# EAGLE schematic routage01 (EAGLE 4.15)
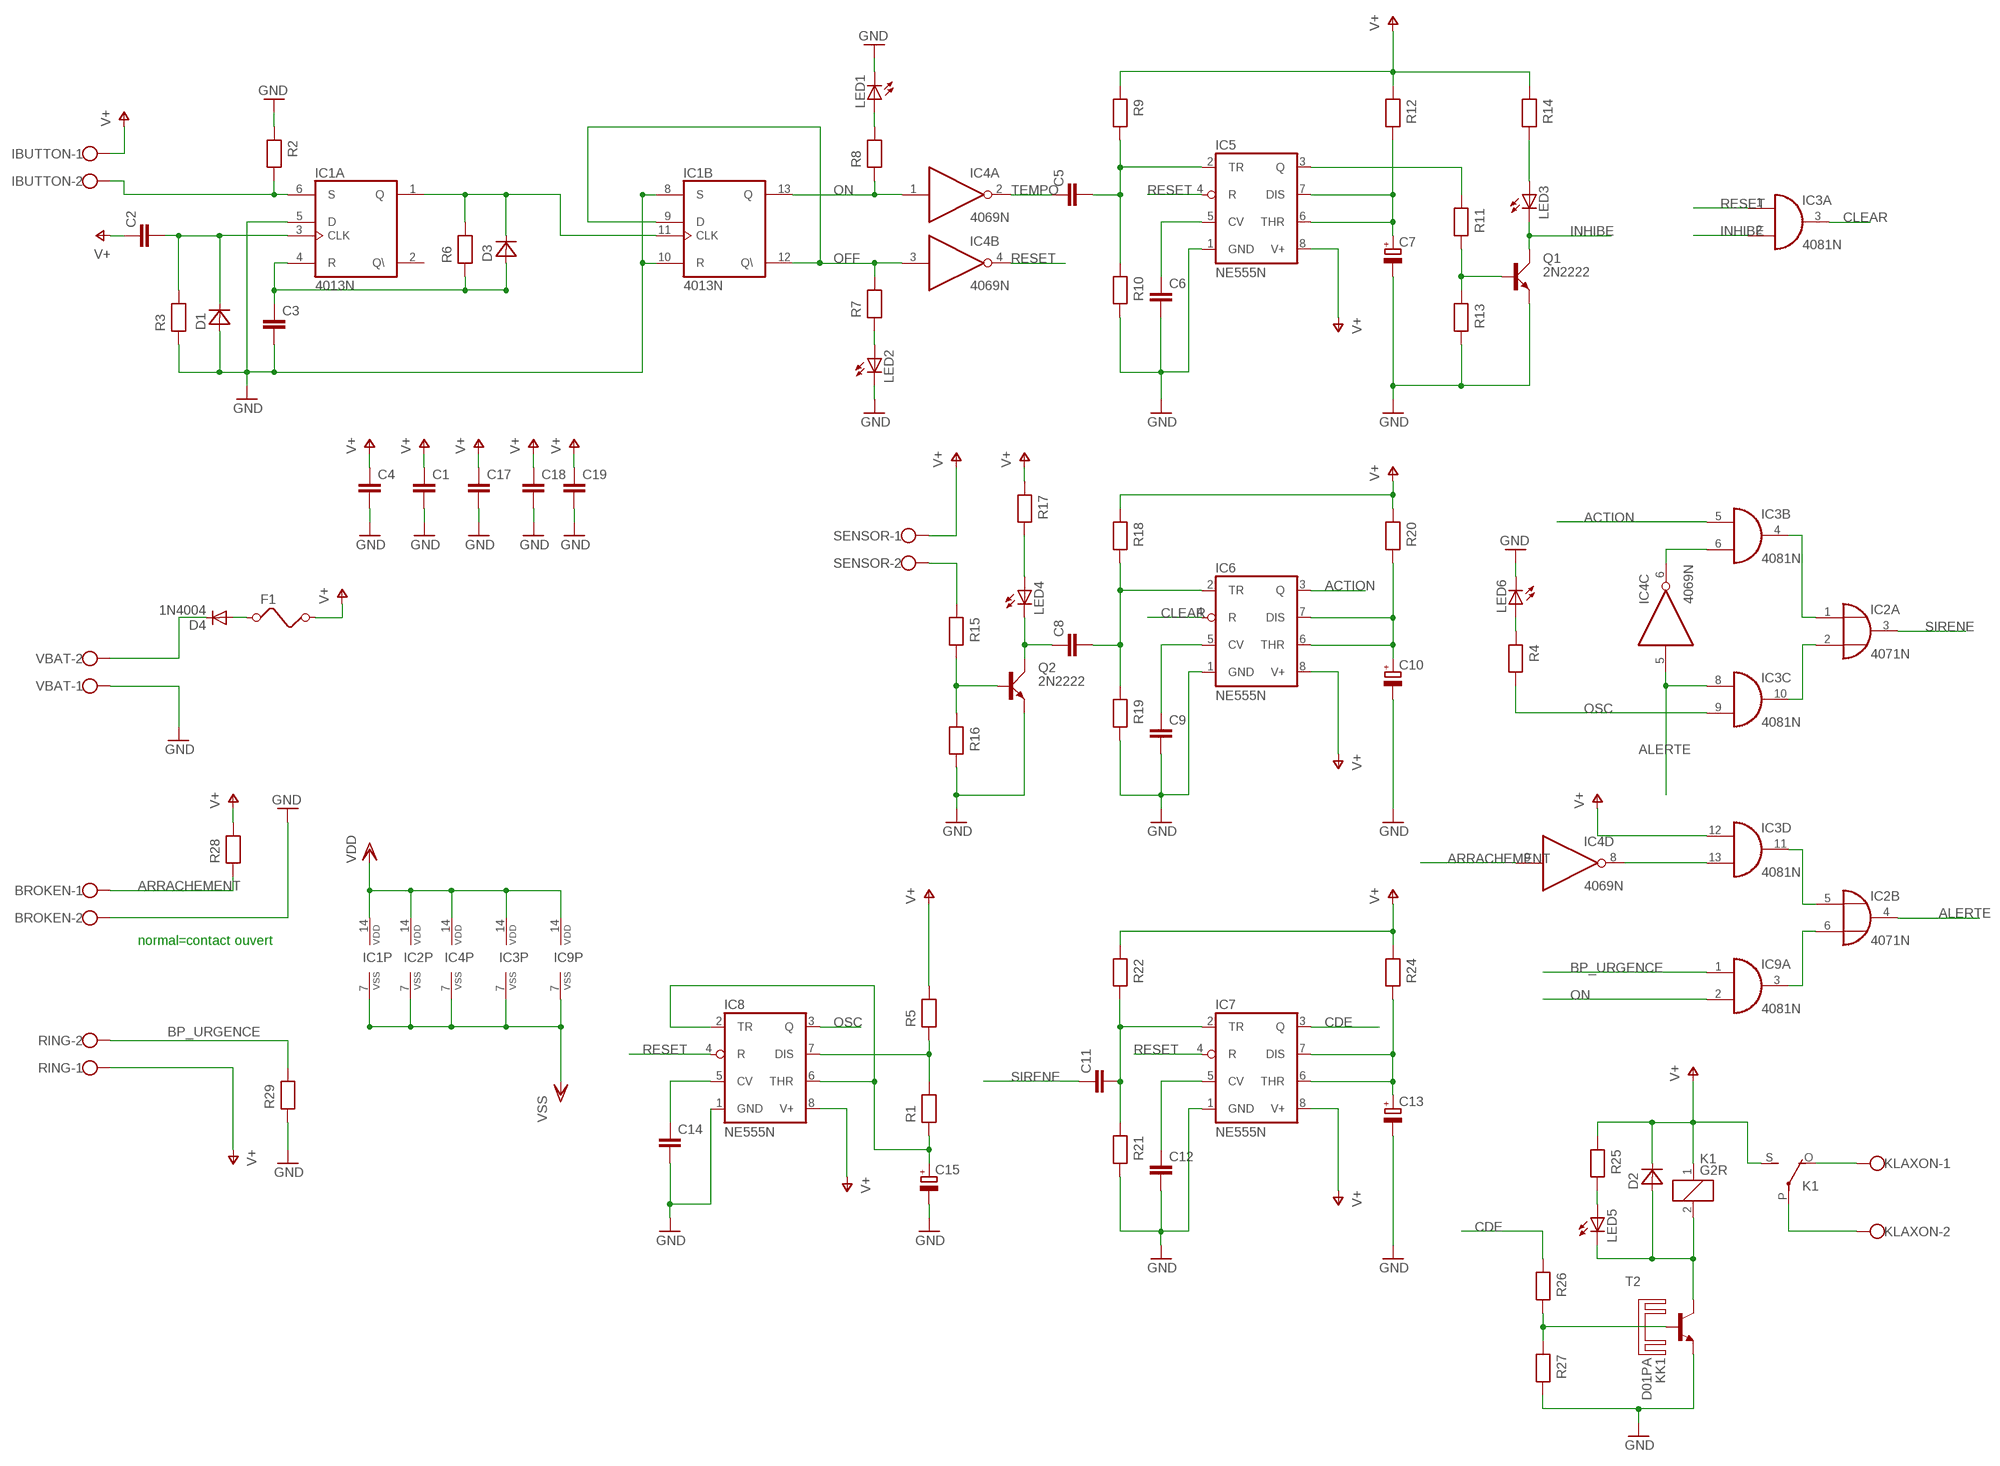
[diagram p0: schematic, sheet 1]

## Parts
BROKEN  W237-02P  [W237-132]
C1  C-EU025-025X050  [C025-025X050]
C2  C-EU025-025X050  [C025-025X050]
C3  C-EU025-025X050  [C025-025X050]
C4  C-EU025-025X050  [C025-025X050]
C5  C-EU025-025X050  [C025-025X050]
C6  C-EU025-025X050  [C025-025X050]
C7  CPOL-EUE5-6  [E5-6]
C8  C-EU025-025X050  [C025-025X050]
C9  C-EU025-025X050  [C025-025X050]
C10  CPOL-EUE5-6  [E5-6]
C11  C-EU025-025X050  [C025-025X050]
C12  C-EU025-025X050  [C025-025X050]
C13  CPOL-EUE5-6  [E5-6]
C14  C-EU025-025X050  [C025-025X050]
C15  CPOL-EUE5-6  [E5-6]
C17  C-EU025-025X050  [C025-025X050]
C18  C-EU025-025X050  [C025-025X050]
C19  C-EU025-025X050  [C025-025X050]
D1  DIODE-7,5  [D-7,5]
D2  DIODE-10  [D-10]
D3  DIODE-7,5  [D-7,5]
D4  1N4004  [DO41-10]
F1  FUSE  [FUSE]
IBUTTON  W237-02P  [W237-132]
IC1  4013N  [DIL14]
IC2  4071N  [DIL14]
IC3  4081N  [DIL14]
IC4  4069N  [DIL14]
IC5  NE555N  [DIL08]
IC6  NE555N  [DIL08]
IC7  NE555N  [DIL08]
IC8  NE555N  [DIL08]
IC9  4081N  [DIL14]
K1  G2R  [G2R]
KK1  D01PA  [D01PA]
KLAXON  W237-02P  [W237-132]
LED1  LED5MM  [LED5MM]
LED2  LED5MM  [LED5MM]
LED3  LED5MM  [LED5MM]
LED4  LED5MM  [LED5MM]
LED5  LED5MM  [LED5MM]
LED6  LED5MM  [LED5MM]
Q1  2N2222  [TO18A]
Q2  2N2222  [TO18A]
R1  RESEU-10  [R-10]
R2  RESEU-10  [R-10]
R3  RESEU-10  [R-10]
R4  RESEU-10  [R-10]
R5  RESEU-10  [R-10]
R6  RESEU-10  [R-10]
R7  RESEU-10  [R-10]
R8  RESEU-10  [R-10]
R9  RESEU-10  [R-10]
R10  RESEU-10  [R-10]
R11  RESEU-10  [R-10]
R12  RESEU-10  [R-10]
R13  RESEU-10  [R-10]
R14  RESEU-10  [R-10]
R15  RESEU-10  [R-10]
R16  RESEU-10  [R-10]
R17  RESEU-10  [R-10]
R18  RESEU-10  [R-10]
R19  RESEU-10  [R-10]
R20  RESEU-10  [R-10]
R21  RESEU-10  [R-10]
R22  RESEU-10  [R-10]
R24  RESEU-10  [R-10]
R25  RESEU-10  [R-10]
R26  RESEU-10  [R-10]
R27  RESEU-10  [R-10]
R28  RESEU-10  [R-10]
R29  RESEU-10  [R-10]
RING  W237-02P  [W237-132]
SENSOR  W237-02P  [W237-132]
T2  -NPN-TO220V  [TO220V]
VBAT  W237-02P  [W237-132]

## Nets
ACTION: IC3.5(B:I0) IC6.3(Q)
ALERTE: IC2.4(B:O) IC3.8(C:I0) IC4.5(C:I)
ARRACHEMENT: BROKEN.1 IC4.9(D:I) R28.1
BP_URGENCE: IC9.1(A:I0) R29.2 RING.2
CDE: IC7.3(Q) R26.1
CLEAR: IC3.3(A:O) IC6.4(R)
GND: BROKEN.2 C1.2 C3.2 C4.2 C6.2 C7.- C9.2 C10.- C12.2 C13.- C14.2 C15.- C17.2 C18.2 C19.2 D1.1(A) IC1.5(A:D) IC1.8(B:S) IC1.10(B:R) IC5.1(GND) IC6.1(GND) IC7.1(GND) IC8.1(GND) LED1.K(C) LED2.K(C) LED6.K(C) Q1.E Q2.E R2.1 R3.1 R10.2 R13.2 R16.2 R19.2 R21.2 R27.2 R29.1 T2.3(E) VBAT.1
INHIBE: IC3.2(A:I1) LED3.K(C) Q1.C
N$1: C3.1 D3.1(A) IC1.4(A:R) R6.1
N$2: C2.2 D1.2(K) IC1.3(A:CLK) R3.2
N$3: LED4.A R17.2
N$4: LED2.A R7.1
N$5: LED1.A R8.2
N$6: IBUTTON.2 IC1.6(A:S) R2.2
N$7: D3.2(K) IC1.1(A:Q) IC1.11(B:CLK) R6.2
N$8: C6.1 IC5.5(CV)
N$9: C7.+ IC5.6(THR) IC5.7(DIS) R12.2
N$10: C8.1 LED4.K(C) Q2.C
N$11: IC5.3(Q) R11.1
N$12: Q1.B R11.2 R13.1
N$13: Q2.B R15.2 R16.1
N$14: C5.2 IC5.2(TR) R9.2 R10.1
N$15: R15.1 SENSOR.2
N$16: C12.1 IC7.5(CV)
N$17: C9.1 IC6.5(CV)
N$18: C8.2 C11.2 IC6.2(TR) IC7.2(TR) R18.2 R19.1 R21.1 R22.2
N$19: LED3.A R14.2
N$20: LED6.A R4.1
N$21: R26.2 R27.1 T2.1(B)
N$22: IC3.6(B:I1) IC4.6(C:O)
N$23: C13.+ IC7.6(THR) IC7.7(DIS) R24.2
N$24: D2.1(A) K1.2 LED5.K(C) T2.2(C)
N$25: LED5.A R25.2
N$26: IC2.2(A:I1) IC3.10(C:O)
N$27: IC2.1(A:I0) IC3.4(B:O)
N$28: C10.+ IC6.6(THR) IC6.7(DIS) R20.2
N$29: IC3.13(D:I1) IC4.8(D:O)
N$30: C14.1 IC8.5(CV)
N$31: IC8.7(DIS) R1.2 R5.1
N$32: IC2.5(B:I0) IC3.11(D:O)
N$33: IC2.6(B:I1) IC9.3(A:O)
N$34: C15.+ IC8.2(TR) IC8.6(THR) R1.1
N$35: D4.A F1.1
N$36: K1.O(2:O) KLAXON.1
N$37: D4.C VBAT.2
N$38: K1.P(2:P) KLAXON.2
OFF: IC1.9(B:D) IC1.12(B:Q\) IC4.3(B:I) R7.2
ON: IC1.13(B:Q) IC4.1(A:I) IC9.2(A:I1) R8.1
OSC: IC3.9(C:I1) IC8.3(Q) R4.2
RESET: IC3.1(A:I0) IC4.4(B:O) IC5.4(R) IC7.4(R) IC8.4(R)
SIRENE: C11.1 IC2.3(A:O)
TEMPO: C5.1 IC4.2(A:O)
V+: C1.1 C2.1 C4.1 C17.1 C18.1 C19.1 D2.2(K) F1.2 IBUTTON.1 IC3.12(D:I0) IC5.8(V+) IC6.8(V+) IC7.8(V+) IC8.8(V+) K1.1 K1.S(2:S) R5.2 R9.1 R12.1 R14.1 R17.1 R18.1 R20.1 R22.1 R24.1 R25.1 R28.2 RING.1 SENSOR.1
VDD: IC1.14(P:VDD) IC2.14(P:VDD) IC3.14(P:VDD) IC4.14(P:VDD) IC9.14(P:VDD)
VSS: IC1.7(P:VSS) IC2.7(P:VSS) IC3.7(P:VSS) IC4.7(P:VSS) IC9.7(P:VSS)
Unconnected: IC1.2(A:Q\) IC2.8(C:I0) IC2.9(C:I1) IC2.10(C:O) IC2.11(D:O) IC2.12(D:I0) IC2.13(D:I1) IC4.10(E:O) IC4.11(E:I) IC4.12(F:O) IC4.13(F:I) IC9.4(B:O) IC9.5(B:I0) IC9.6(B:I1) IC9.8(C:I0) IC9.9(C:I1) IC9.10(C:O) IC9.11(D:O) IC9.12(D:I0) IC9.13(D:I1)

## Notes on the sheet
- normal=contact ouvert

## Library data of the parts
BROKEN IBUTTON KLAXON RING SENSOR VBAT = con-wago-508:W237-02P: WAGO SREW CLAMP
C1-C6 C8 C9 C11 C12 C14 C17-C19 = rcl:C-EU: CAPACITOR, European symbol
C7 C10 C13 C15 = rcl:CPOL-EU: POLARIZED CAPACITOR, European symbol
D1 D3 = discrete:DIODE-7,5
D2 = discrete:DIODE-10
D4 = diode:1N4004: DIODE
F1 = special:FUSE: FUSE
IC1 = 40xx:4013: Dual D FLIP FLOP, set/reset
IC2 = 40xx:4071: Quad 2-input OR
IC3 IC9 = 40xx:4081: Quad 2-input AND
IC4 = 40xx:4069: Hex INVERTER
IC5-IC8 = linear:*555: TIMER
K1 = relay:G2R: RELAY 1 x switch, Omron
KK1 = heatsink:D01PA: HEATSINK
LED1-LED6 = led:LED: LED
Q1 Q2 = transistor-small-signal:2N2222: NPN TRANSISTOR
R1-R22 R24-R29 = discrete:RESEU-10
T2 = transistor:*-NPN-: NPN Transistror

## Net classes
0 default: width 0.5 mm, drill 0.5 mm, clearance 0.8 mm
